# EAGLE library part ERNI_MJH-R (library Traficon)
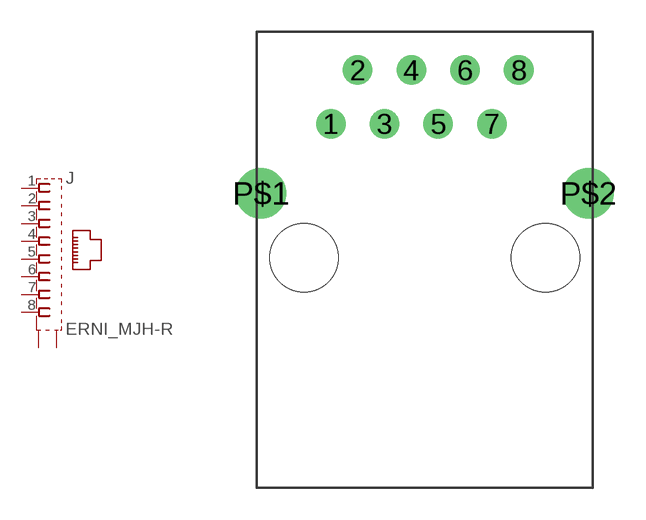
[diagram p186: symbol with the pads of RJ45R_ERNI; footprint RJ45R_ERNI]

Designator prefix J

## ERNI_MJH-R  [RJ45R_ERNI]
1  1  pas
2  2  pas
3  3  pas
4  4  pas
5  5  pas
6  6  pas
7  7  pas
8  8  pas
P$1  S1  pas
P$2  S2  pas

## Footprint RJ45R_ERNI (pad centres in mm)
drill 0.889 round: 1 -4.445,6.35; 2 -3.175,8.89; 3 -1.905,6.35; 4 -0.635,8.89; 5 0.635,6.35; 6 1.905,8.89; 7 3.175,6.35; 8 4.445,8.89
drill 1.6 round: P$1 -7.745,3.05; P$2 7.745,3.05
hole 3.251 at -5.715,0
hole 3.251 at 5.715,0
